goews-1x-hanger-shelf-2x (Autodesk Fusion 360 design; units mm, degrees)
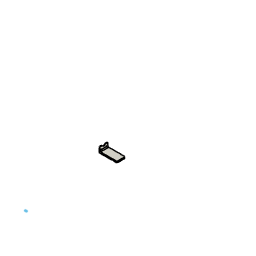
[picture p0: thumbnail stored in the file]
base_feature "Base Feature2"
base_feature "Base Feature1" bodies "Single Plate Blank"
offset_faces "OffsetFaces1" distance 0.026
fillet "Fillet1" radius 3 named "d2_1"
box_primitive "BoxPrimitive2" DistanceX 4 DistanceY 41.6 DistanceZ 46 (= "4 mm + 42 mm") OffsetDistanceX 0 OffsetDistanceY 0
chamfer "Chamfer2" distance 4
fillet "Fillet3" radius 3
delete_face "DeleteFace1"
split "Split1" bodies "Single Plate Blank (1)"
delete_face "DeleteFace2"
offset_faces "OffsetFaces2" distance 42
fillet "Fillet4" radius 3.75
combine "Combine1" bodies "Single Plate Blank"
chamfer "Chamfer3" distance 4
offset_faces "OffsetFaces3" distance 2.328
move_face "MoveFace3"
extrude "Extrude1" cut sketch "Reconstructed-Sketch3" blind -1060
named bodies: "Single Plate Blank", "Single Plate Blank (1)"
